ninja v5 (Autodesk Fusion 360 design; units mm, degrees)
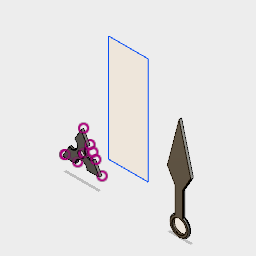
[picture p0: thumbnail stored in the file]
sketch "Sketch1"
  line L1 (7.4833, 13) -> (7.5, 13)
  line L2 (-7.5, 13) -> (-7.4833, 13)
  line L3 (22.5627, 82.94) -> (7.5286, 56.979)
  line L4 (-22.4372, 82.9992) -> (-8.4686, 58.7312)
  line L5 (0.1366, 170.1012) -> (22.5627, 82.94)
  line L6 (-22.4372, 82.9992) -> (0.1366, 170.1012)
  line L7 (-207.5, 21.6506) -> (-220, 0)
  line L8 (-185, 60.6218) -> (-197.5, 38.9711)
  line L9 (-162.5, 21.6506) -> (-150, 0)
  line L10 (-185, 60.6218) -> (-172.5, 38.9711)
  line L11 (-175, 0) -> (-150, 0)
  line L12 (-220, 0) -> (-195, 0)
  line L13 (-195, 0) -> (-220, 0)
  line L14 (-150, 0) -> (-175, 0)
  line L15 (-8.4686, 11.7312) -> (-8.4686, 58.7312)
  line L16 (7.5286, 12.1182) -> (7.5286, 56.979)
  line L17 (-40.2879, -25) -> (-50, -25)
  circle C1 centre (-0.0533, -5.3035) radius 12.5
  arc A1 centre (-202.5, 30.3109) radius 10 clockwise from (-197.5, 38.9711) to (-207.5, 21.6506)
  arc A2 centre (-167.5, 30.3109) radius 10 clockwise from (-162.5, 21.6506) to (-172.5, 38.9711)
  arc A3 centre (-185, 0) radius 10 clockwise from (-195, 0) to (-175, 0)
  circle C2 centre (-185, 20) radius 5
  arc A4 centre (-0.0533, -5.3035) radius 19 clockwise from (7.5286, 12.1182) to (-8.4686, 11.7312)
extrude "Extrude1" new body sketch "Sketch1" profile of L3 L4 L5 L6 C1 L12 L8 L10 A1 A2 A3 C2 A4 L15 L16 blind 5
fillet "Fillet1" radius 1
fillet "Fillet2" radius 1
fillet "Fillet3" radius 2
fillet "Fillet4" radius 2
fillet "Fillet5" radius 1
fillet "Fillet6" radius 1
fillet "Fillet7" radius 1
fillet "Fillet8" radius 1
fillet "Fillet9" radius 1
fillet "Fillet10" radius 1
fillet "Fillet11" radius 1
fillet "Fillet12" radius 1
sketch "Sketch2"
  line L1 (-137.8155, 33.4896) -> (-62.9557, 33.4896)
  line L2 (-137.8155, 234.8841) -> (-137.8155, 33.4896)
  line L3 (-62.9557, 234.8841) -> (-137.8155, 234.8841)
  line L4 (-62.9557, 33.4896) -> (-62.9557, 234.8841)
  line L5 (-196, 0) -> (-220, 0)
  circle C1 centre (-185, 20) radius 6
  arc A1 centre (-167.5, 30.3109) radius 11 clockwise from (-162, 20.7846) to (-173, 39.8372)
  point P6 (-220, 0)
  point P7 (-150, 0)
  point P8 (-185, 60.6218)
  point P9 (-220, 0)
  point P10 (-196, 0)
  dimension "d46" distance P6 P7 = 70
  dimension "d47" distance P6 P8 = 70
  dimension "d48" distance P9 P10 = 24
  dimension "d49" diameter C1 = 12
  dimension "d50" radius A1 = 11
sketch "Sketch3" plane through (0, 0, 5) normal (0, 0, 1) x axis (1, 0, 0)
  line L1 (-7.4686, 58.9985) -> (-22.079, 84.3814)
  line L2 (-7.4686, 9.994) -> (-7.4686, 58.9985)
  line L3 (6.5286, 57.2476) -> (6.5286, 10.3707)
  line L4 (22.2073, 84.3216) -> (6.5286, 57.2476)
  line L5 (0.1366, 170.1012) -> (22.2073, 84.3216)
  line L6 (-22.079, 84.3814) -> (0.1366, 170.1012)
  circle C1 centre (-0.0533, -5.3035) radius 13.5
  arc A1 centre (-0.0533, -5.3035) radius 17 clockwise from (6.5286, 10.3707) to (-7.4686, 9.994)
  point P2 (-0.0533, -5.3035)
  point P9 (0.1366, 170.1012)
  point P6 (6.5286, 10.3707)
  point P7 (6.5286, 57.2476)
  dimension "d51" distance P2 P9 = 175.4046
  dimension "d52" distance P6 P7 = 46.877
